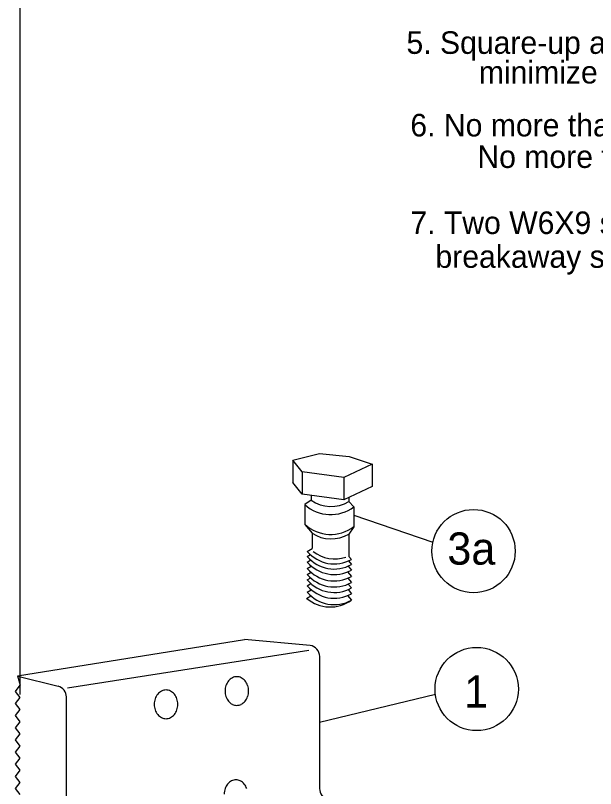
# Model space of a CAD drawing. Extents: x 12.3 to 19.6, y 5.8 to 16.1.
# Drawn here: x 14.208 to 15.752, y 8.839 to 10.897 of the extents above; entities that cross this region are included whole.
import ezdxf

# ---------------------------------------------------------------- set-up
doc = ezdxf.new("R2010")
doc.units = 0
doc.layers.add('DETL-LINE', color=7, linetype='Continuous')
doc.layers.add('DETL-NOTE', color=7, linetype='Continuous')

msp = doc.modelspace()

# ---------------------------------------------------------------- linework, layer by layer
at = {"layer": 'DETL-LINE'}
for p, q in [((14.2196, 12.1081), (14.2196, 9.0896)), ((14.9465, 9.7132), (15.0174, 9.7305)), ((15.0174, 9.7305), (15.0962, 9.7232)), ((15.0962, 9.7232), (15.1572, 9.7027)), ((14.9711, 9.6821), (14.9465, 9.7132)), ((14.9465, 9.7132), (14.9465, 9.6537)), ((15.1572, 9.7027), (15.0817, 9.6669)), ((15.1572, 9.7027), (15.1572, 9.6431)), ((14.9711, 9.6821), (14.9711, 9.6226)), ((15.0817, 9.6669), (14.9711, 9.6821)), ((14.9711, 9.6226), (14.9465, 9.6537)), ((15.0817, 9.6669), (15.0817, 9.6073)), ((15.1572, 9.6431), (15.0817, 9.6073)), ((15.0817, 9.6073), (14.9711, 9.6226)), ((14.9953, 9.6192), (14.9953, 9.6064)), ((15.0956, 9.6139), (15.0956, 9.6028)), ((14.9953, 9.6064), (14.9783, 9.595)), ((14.9783, 9.595), (14.9783, 9.5423)), ((15.0956, 9.6028), (15.109, 9.5888)), ((15.109, 9.5888), (15.109, 9.5361)), ((14.9783, 9.5423), (14.9978, 9.5185)), ((15.109, 9.5361), (15.0956, 9.5165)), ((14.9978, 9.5185), (14.9978, 9.4779)), ((15.0956, 9.5165), (15.0956, 9.4571)), ((14.985, 9.4702), (14.9978, 9.4779)), ((14.985, 9.4567), (14.9932, 9.4616)), ((14.985, 9.4419), (14.994, 9.4474)), ((15.0956, 9.4571), (15.1024, 9.449)), ((14.985, 9.4248), (14.9956, 9.4312)), ((15.0936, 9.4311), (15.1024, 9.4207)), ((15.0944, 9.445), (15.1024, 9.4355)), ((14.985, 9.4089), (14.9948, 9.4148)), ((15.0922, 9.4157), (15.1024, 9.4036)), ((14.985, 9.3942), (14.994, 9.3996)), ((15.0929, 9.3989), (15.1024, 9.3877)), ((14.985, 9.3788), (14.9944, 9.3845)), ((14.985, 9.3617), (14.9956, 9.3681)), ((15.0933, 9.3684), (15.1024, 9.3576)), ((15.0936, 9.3833), (15.1024, 9.3729)), ((14.9832, 9.3452), (14.9945, 9.352)), ((15.0922, 9.3526), (15.1024, 9.3405)), ((14.2138, 9.1393), (14.8178, 9.2355)), ((14.9923, 9.2197), (14.8178, 9.2355)), ((14.3466, 9.1067), (14.9888, 9.2075)), ((15.0178, 9.1906), (15.0178, 8.8392)), ((14.2138, 9.1393), (14.221, 9.1138)), ((14.2142, 9.1377), (14.3216, 9.1112)), ((14.2083, 9.0976), (14.221, 9.1138)), ((14.221, 9.0815), (14.2083, 9.0976)), ((14.2083, 9.0653), (14.221, 9.0815)), ((14.3439, 8.6354), (14.3439, 9.0827)), ((14.221, 9.0492), (14.2083, 9.0653)), ((14.2083, 9.033), (14.221, 9.0492)), ((14.221, 9.0168), (14.2083, 9.033)), ((14.2083, 9.0007), (14.221, 9.0168)), ((14.221, 8.9845), (14.2083, 9.0007)), ((14.2083, 8.9684), (14.221, 8.9845)), ((14.221, 8.9522), (14.2083, 8.9684)), ((14.2083, 8.9361), (14.221, 8.9522)), ((14.221, 8.9199), (14.2083, 8.9361)), ((14.2083, 8.9037), (14.221, 8.9199)), ((14.221, 8.8876), (14.2083, 8.9037)), ((14.2083, 8.8714), (14.221, 8.8876)), ((14.221, 8.8553), (14.2083, 8.8714)), ((14.2083, 8.8391), (14.221, 8.8553)), ((14.221, 8.823), (14.2083, 8.8391))]:
    msp.add_line(p, q, dxfattribs=at)
for centre, radius, start, end in [((15.0474, 9.6705), 0.1023, 227.5174, 307.055), ((15.0483, 9.6829), 0.093, 235.2965, 300.5732), ((15.0474, 9.6178), 0.1023, 227.5174, 307.055), ((15.0483, 9.5966), 0.093, 237.1441, 300.5732), ((15.0565, 9.5305), 0.0935, 220.0991, 299.4052), ((15.0579, 9.542), 0.092, 231.2376, 288.847), ((15.0565, 9.5169), 0.0935, 220.0991, 299.4052), ((15.0565, 9.5022), 0.0935, 220.0991, 299.4052), ((15.0565, 9.4851), 0.0935, 220.0991, 299.4052), ((15.0565, 9.4691), 0.0935, 220.0991, 299.4052), ((15.0565, 9.4544), 0.0935, 220.0991, 299.4052), ((15.0565, 9.4391), 0.0935, 220.0991, 299.4052), ((15.0459, 9.4198), 0.0974, 229.9667, 305.5002), ((15.0565, 9.422), 0.0935, 220.0991, 299.4052), ((14.9885, 9.1906), 0.0294, 0, 82.4728), ((14.805, 9.101), 0.0386, 140.6296, 161.2281), ((14.8003, 9.1049), 0.0325, 116.7848, 140.6296), ((14.7973, 9.1108), 0.0259, 90, 116.7848), ((14.7973, 9.1108), 0.0259, 63.2152, 90), ((14.7943, 9.1049), 0.0325, 39.3704, 63.2152), ((14.7896, 9.101), 0.0386, 18.7719, 39.3704), ((14.3145, 9.0827), 0.0294, 0, 76.1221), ((14.612, 9.0695), 0.0325, 116.7848, 140.6296), ((14.609, 9.0754), 0.0259, 90, 116.7848), ((14.609, 9.0754), 0.0259, 63.2152, 90), ((14.606, 9.0695), 0.0325, 39.3704, 63.2152), ((14.8124, 9.0985), 0.0464, 161.2281, 180), ((14.8124, 9.0985), 0.0464, 180, 198.7719), ((14.7823, 9.0985), 0.0464, 0, 18.7719), ((14.7823, 9.0985), 0.0464, 341.2281, 360), ((14.624, 9.0631), 0.0464, 161.2281, 180), ((14.6166, 9.0656), 0.0386, 140.6296, 161.2281), ((14.6013, 9.0656), 0.0386, 18.7719, 39.3704), ((14.5939, 9.0631), 0.0464, 0, 18.7719), ((14.805, 9.096), 0.0386, 198.7719, 219.3704), ((14.7896, 9.096), 0.0386, 320.6296, 341.2281), ((14.624, 9.0631), 0.0464, 180, 198.7719), ((14.5939, 9.0631), 0.0464, 341.2281, 360), ((14.8003, 9.0922), 0.0325, 219.3704, 243.2152), ((14.7973, 9.0862), 0.0259, 243.2152, 270), ((14.7973, 9.0862), 0.0259, 270, 296.7848), ((14.7943, 9.0922), 0.0325, 296.7848, 320.6296), ((14.6166, 9.0606), 0.0386, 198.7719, 219.3704), ((14.612, 9.0568), 0.0325, 219.3704, 243.2152), ((14.606, 9.0568), 0.0325, 296.7848, 320.6296), ((14.6013, 9.0606), 0.0386, 320.6296, 341.2281), ((14.609, 9.0508), 0.0259, 243.2152, 270), ((14.609, 9.0508), 0.0259, 270, 296.7848), ((14.8027, 8.8265), 0.0386, 140.6296, 161.2281), ((14.798, 8.8304), 0.0325, 116.7848, 140.6296), ((14.795, 8.8363), 0.0259, 90, 116.7848), ((14.795, 8.8363), 0.0259, 63.2152, 90), ((14.792, 8.8304), 0.0325, 39.3704, 63.2152), ((14.7873, 8.8265), 0.0386, 18.7719, 39.3704), ((14.8101, 8.824), 0.0464, 161.2281, 180), ((15.0517, 8.8392), 0.0339, 180, 248.4327)]:
    msp.add_arc(centre, radius, start, end, dxfattribs=at)
at = {"layer": 'DETL-NOTE'}
for p, q in [((15.109, 9.5669), (15.3191, 9.4945)), ((15.0178, 9.0158), (15.3258, 9.0899))]:
    msp.add_line(p, q, dxfattribs=at)
for centre in [(15.4273, 9.4711), (15.4357, 9.1039)]:
    msp.add_circle(centre, 0.1108, dxfattribs=at)

# ---------------------------------------------------------------- texts
for s, height, p in [('5. Square-up and level individual components, particularly Anchors to', 0.06, (15.2488, 10.7948)), ('minimize the need for shimming between the Couplings and Anchors.', 0.06, (15.4413, 10.7159)), ('6. No more than two shims shall be placed under any one coupling.', 0.06, (15.2591, 10.5751)), ('No more than three shims underneath any pair of couplings.', 0.06, (15.4375, 10.4911)), ("7. Two W6X9 sign posts may be placed within 7' when utilizing", 0.06, (15.2591, 10.3152)), ("   breakaway support system 'A'.", 0.06, (15.2591, 10.2252)), ('3a', 0.0858, (15.3576, 9.435)), ('1', 0.0858, (15.4021, 9.0543))]:
    msp.add_text(s, height=height, dxfattribs=at).set_placement(p)

doc.saveas('drawing.dxf')
